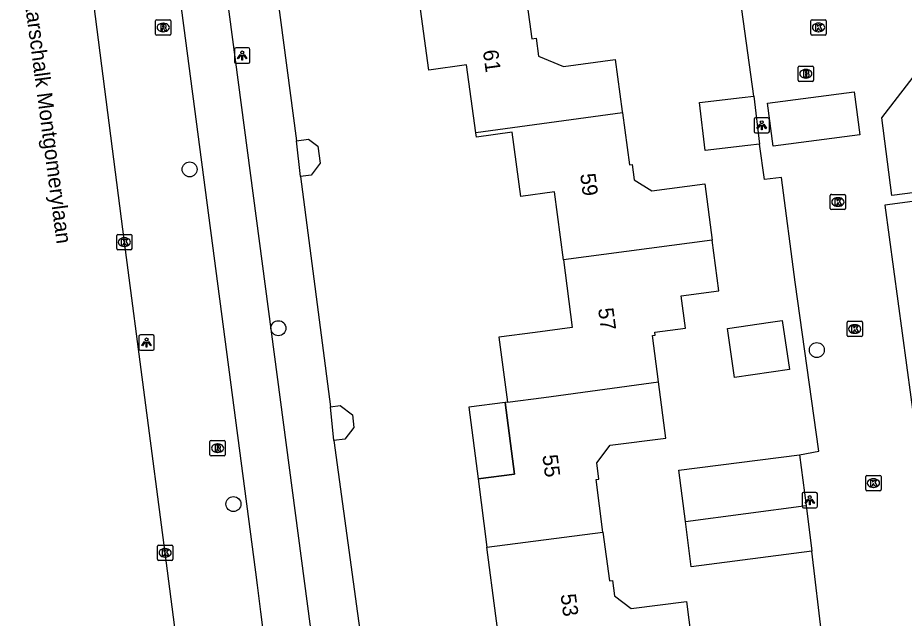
# Model space of a CAD drawing. Extents: x 161084 to 161928, y 385355 to 386522.
# Drawn here: x 161147.4 to 161205.4, y 386075.9 to 386115.2 of the extents above; entities that cross this region are included whole.
import ezdxf

# ---------------------------------------------------------------- set-up
doc = ezdxf.new("R2010")
doc.units = 0
for name, color, linetype in [('IMGEO_Boom', 7, 'Continuous'), ('IMGEO_Brandkraan', 7, 'Continuous'), ('IMGEO_Fietspad_gesloten', 7, 'Continuous'), ('IMGEO_Kolk', 7, 'Continuous'), ('IMGEO_Lichtpunt', 7, 'Continuous'), ('IMGEO_Openbare_ruimte_label', 7, 'Continuous'), ('IMGEO_OVBaan_gesloten', 7, 'Continuous'), ('IMGEO_Pand', 7, 'Continuous'), ('IMGEO_Pand_nummerreeks', 7, 'Continuous'), ('IMGEO_Pand_overbouw', 7, 'Continuous'), ('IMGEO_Rijbaan_lokaal_open', 7, 'Continuous'), ('IMGEO_Rioolput', 7, 'Continuous'), ('IMGEO_Voetpad_open', 7, 'Continuous')]:
    doc.layers.add(name, color=color, linetype=linetype)

msp = doc.modelspace()

# ---------------------------------------------------------------- linework, layer by layer
at = {"layer": 'IMGEO_Boom'}
for centre in [(161158.68, 386105.239), (161164.481, 386094.854), (161199.666, 386093.427), (161161.542, 386083.355)]:
    msp.add_circle(centre, 0.489, dxfattribs=at)
at = {"layer": 'IMGEO_Brandkraan'}
for p, q in [((161198.449, 386111.065), (161198.449, 386111.917)), ((161198.524, 386111.991), (161199.376, 386111.991)), ((161199.45, 386111.917), (161199.45, 386111.065)), ((161198.96, 386111.211), (161198.935, 386111.211)), ((161198.937, 386111.771), (161198.962, 386111.771)), ((161199.376, 386110.991), (161198.524, 386110.991))]:
    msp.add_line(p, q, dxfattribs=at)
for points in [[(161198.449, 386111.065), (161198.449, 386111.917)], [(161198.524, 386111.991), (161199.376, 386111.991)], [(161199.45, 386111.917), (161199.45, 386111.065)], [(161198.797, 386111.691), (161198.797, 386111.291), (161199.01, 386111.291)], [(161199.028, 386111.691), (161198.797, 386111.691)], [(161198.976, 386111.61), (161198.922, 386111.61), (161198.922, 386111.534)], [(161198.922, 386111.534), (161198.975, 386111.534)], [(161198.984, 386111.458), (161198.922, 386111.458), (161198.922, 386111.377)], [(161198.922, 386111.377), (161198.984, 386111.377)], [(161199.376, 386110.991), (161198.524, 386110.991)]]:
    msp.add_lwpolyline(points, dxfattribs=at)
for centre, radius, start, end in [((161198.526, 386111.915), 0.0765, 91.55205, 178.44795), ((161198.526, 386111.915), 0.0765, 91.55205, 178.44795), ((161199.374, 386111.915), 0.0765, 1.55205, 88.44795), ((161199.374, 386111.915), 0.0765, 1.55205, 88.44795), ((161198.977, 386111.572), 0.0379, 267.82845, 90.93552), ((161198.985, 386111.417), 0.0404, 269.87594, 90.50774), ((161199.016, 386111.542), 0.251, 268.66757, 293.53466), ((161199.032, 386111.546), 0.145, 59.4692, 91.53667), ((161199.057, 386111.593), 0.0922, 285.51372, 58.15012), ((161199.062, 386111.401), 0.105, 301.31148, 78.98903), ((161198.526, 386111.067), 0.0765, 181.55205, 268.44795), ((161198.526, 386111.067), 0.0765, 181.55205, 268.44795), ((161199.374, 386111.067), 0.0765, 271.55205, 358.44795), ((161199.374, 386111.067), 0.0765, 271.55205, 358.44795)]:
    msp.add_arc(centre, radius, start, end, dxfattribs=at)
for centre, major_axis, ratio, start_param, end_param in [((161198.936, 386111.491), (-0.387, 0.002), 0.722429, 4.712389, 7.853982), ((161198.961, 386111.491), (-0.39, 0.002), 0.717154, 1.570796, 4.712389)]:
    msp.add_ellipse(centre, major_axis=major_axis, ratio=ratio, start_param=start_param, end_param=end_param, dxfattribs=at)
at = {"layer": 'IMGEO_Fietspad_gesloten'}
for points in [[(161163.009, 386078.911), (161157.717, 386119.144), (161156.332, 386131.161), (161154.639, 386141.624)], [(161166.599, 386075.195), (161159.109, 386131.85), (161158.613, 386135.495), (161158.527, 386136.476), (161158.508, 386136.957), (161158.694, 386138.756), (161158.914, 386139.531)]]:
    msp.add_lwpolyline(points, dxfattribs=at)
msp.add_arc((160918.944, 386047.246), 246.11, 0.90262, 7.39227, dxfattribs=at)
at = {"layer": 'IMGEO_Kolk'}
for p, q in [((161199.277, 386114.093), (161199.277, 386114.945)), ((161199.352, 386115.019), (161200.204, 386115.019)), ((161199.765, 386114.799), (161199.79, 386114.799)), ((161200.278, 386114.945), (161200.278, 386114.093)), ((161199.788, 386114.239), (161199.763, 386114.239)), ((161200.204, 386114.019), (161199.352, 386114.019)), ((161200.544, 386102.68), (161200.544, 386103.532)), ((161200.619, 386103.606), (161201.471, 386103.606)), ((161201.032, 386103.386), (161201.057, 386103.386)), ((161201.545, 386103.532), (161201.545, 386102.68)), ((161201.471, 386102.606), (161200.619, 386102.606)), ((161201.055, 386102.826), (161201.03, 386102.826)), ((161153.911, 386100.059), (161153.911, 386100.911)), ((161153.986, 386100.985), (161154.838, 386100.985)), ((161154.912, 386100.911), (161154.912, 386100.059)), ((161154.422, 386100.205), (161154.397, 386100.205)), ((161154.399, 386100.765), (161154.424, 386100.765)), ((161154.838, 386099.985), (161153.986, 386099.985)), ((161201.641, 386094.377), (161201.641, 386095.229)), ((161201.716, 386095.303), (161202.568, 386095.303)), ((161202.129, 386095.083), (161202.154, 386095.083)), ((161202.642, 386095.229), (161202.642, 386094.377)), ((161202.152, 386094.523), (161202.127, 386094.523)), ((161202.568, 386094.303), (161201.716, 386094.303)), ((161202.867, 386084.303), (161202.867, 386085.155)), ((161202.942, 386085.229), (161203.794, 386085.229)), ((161203.868, 386085.155), (161203.868, 386084.303)), ((161203.355, 386085.009), (161203.38, 386085.009)), ((161203.794, 386084.229), (161202.942, 386084.229)), ((161203.378, 386084.449), (161203.353, 386084.449)), ((161156.578, 386079.744), (161156.578, 386080.596)), ((161156.653, 386080.67), (161157.505, 386080.67)), ((161157.579, 386080.596), (161157.579, 386079.744)), ((161157.066, 386080.45), (161157.091, 386080.45)), ((161157.505, 386079.67), (161156.653, 386079.67)), ((161157.089, 386079.89), (161157.064, 386079.89))]:
    msp.add_line(p, q, dxfattribs=at)
for points in [[(161199.277, 386114.093), (161199.277, 386114.945)], [(161199.352, 386115.019), (161200.204, 386115.019)], [(161199.598, 386114.719), (161199.721, 386114.719), (161199.721, 386114.568), (161199.851, 386114.719), (161200.015, 386114.719), (161199.869, 386114.568), (161200.022, 386114.319), (161199.87, 386114.319), (161199.785, 386114.483), (161199.721, 386114.416), (161199.721, 386114.319), (161199.598, 386114.319), (161199.598, 386114.719)], [(161200.278, 386114.945), (161200.278, 386114.093)], [(161200.204, 386114.019), (161199.352, 386114.019)], [(161200.544, 386102.68), (161200.544, 386103.532)], [(161200.619, 386103.606), (161201.471, 386103.606)], [(161200.865, 386103.306), (161200.988, 386103.306), (161200.988, 386103.155), (161201.118, 386103.306), (161201.282, 386103.306), (161201.136, 386103.155), (161201.289, 386102.906), (161201.137, 386102.906), (161201.052, 386103.07), (161200.988, 386103.003), (161200.988, 386102.906), (161200.865, 386102.906), (161200.865, 386103.306)], [(161201.545, 386103.532), (161201.545, 386102.68)], [(161201.471, 386102.606), (161200.619, 386102.606)], [(161153.911, 386100.059), (161153.911, 386100.911)], [(161153.986, 386100.985), (161154.838, 386100.985)], [(161154.912, 386100.911), (161154.912, 386100.059)], [(161154.232, 386100.685), (161154.355, 386100.685), (161154.355, 386100.534), (161154.485, 386100.685), (161154.649, 386100.685), (161154.503, 386100.534), (161154.656, 386100.285), (161154.504, 386100.285), (161154.419, 386100.449), (161154.355, 386100.382), (161154.355, 386100.285), (161154.232, 386100.285), (161154.232, 386100.685)], [(161154.838, 386099.985), (161153.986, 386099.985)], [(161201.641, 386094.377), (161201.641, 386095.229)], [(161201.716, 386095.303), (161202.568, 386095.303)], [(161201.962, 386095.003), (161202.085, 386095.003), (161202.085, 386094.852), (161202.215, 386095.003), (161202.379, 386095.003), (161202.233, 386094.852), (161202.386, 386094.603), (161202.234, 386094.603), (161202.149, 386094.767), (161202.085, 386094.7), (161202.085, 386094.603), (161201.962, 386094.603), (161201.962, 386095.003)], [(161202.642, 386095.229), (161202.642, 386094.377)], [(161202.568, 386094.303), (161201.716, 386094.303)], [(161202.867, 386084.303), (161202.867, 386085.155)], [(161202.942, 386085.229), (161203.794, 386085.229)], [(161203.868, 386085.155), (161203.868, 386084.303)], [(161203.188, 386084.929), (161203.311, 386084.929), (161203.311, 386084.778), (161203.441, 386084.929), (161203.605, 386084.929), (161203.459, 386084.778), (161203.612, 386084.529), (161203.46, 386084.529), (161203.375, 386084.693), (161203.311, 386084.626), (161203.311, 386084.529), (161203.188, 386084.529), (161203.188, 386084.929)], [(161203.794, 386084.229), (161202.942, 386084.229)], [(161156.578, 386079.744), (161156.578, 386080.596)], [(161156.653, 386080.67), (161157.505, 386080.67)], [(161157.579, 386080.596), (161157.579, 386079.744)], [(161156.899, 386080.37), (161157.022, 386080.37), (161157.022, 386080.219), (161157.152, 386080.37), (161157.316, 386080.37), (161157.17, 386080.219), (161157.323, 386079.97), (161157.171, 386079.97), (161157.086, 386080.134), (161157.022, 386080.067), (161157.022, 386079.97), (161156.899, 386079.97), (161156.899, 386080.37)], [(161157.505, 386079.67), (161156.653, 386079.67)]]:
    msp.add_lwpolyline(points, dxfattribs=at)
for centre, start, end in [((161199.354, 386114.943), 91.55205, 178.44795), ((161199.354, 386114.943), 91.55205, 178.44795), ((161200.202, 386114.943), 1.55205, 88.44795), ((161200.202, 386114.943), 1.55205, 88.44795), ((161199.354, 386114.095), 181.55205, 268.44795), ((161199.354, 386114.095), 181.55205, 268.44795), ((161200.202, 386114.095), 271.55205, 358.44795), ((161200.202, 386114.095), 271.55205, 358.44795), ((161200.621, 386103.53), 91.55205, 178.44795), ((161200.621, 386103.53), 91.55205, 178.44795), ((161201.469, 386103.53), 1.55205, 88.44795), ((161201.469, 386103.53), 1.55205, 88.44795), ((161200.621, 386102.682), 181.55205, 268.44795), ((161200.621, 386102.682), 181.55205, 268.44795), ((161201.469, 386102.682), 271.55205, 358.44795), ((161201.469, 386102.682), 271.55205, 358.44795), ((161153.988, 386100.909), 91.55205, 178.44795), ((161153.988, 386100.909), 91.55205, 178.44795), ((161154.836, 386100.909), 1.55205, 88.44795), ((161154.836, 386100.909), 1.55205, 88.44795), ((161153.988, 386100.061), 181.55205, 268.44795), ((161153.988, 386100.061), 181.55205, 268.44795), ((161154.836, 386100.061), 271.55205, 358.44795), ((161154.836, 386100.061), 271.55205, 358.44795), ((161201.718, 386095.227), 91.55205, 178.44795), ((161201.718, 386095.227), 91.55205, 178.44795), ((161202.566, 386095.227), 1.55205, 88.44795), ((161202.566, 386095.227), 1.55205, 88.44795), ((161201.718, 386094.379), 181.55205, 268.44795), ((161201.718, 386094.379), 181.55205, 268.44795), ((161202.566, 386094.379), 271.55205, 358.44795), ((161202.566, 386094.379), 271.55205, 358.44795), ((161202.944, 386085.153), 91.55205, 178.44795), ((161202.944, 386085.153), 91.55205, 178.44795), ((161203.792, 386085.153), 1.55205, 88.44795), ((161203.792, 386085.153), 1.55205, 88.44795), ((161202.944, 386084.305), 181.55205, 268.44795), ((161202.944, 386084.305), 181.55205, 268.44795), ((161203.792, 386084.305), 271.55205, 358.44795), ((161203.792, 386084.305), 271.55205, 358.44795), ((161156.655, 386080.594), 91.55205, 178.44795), ((161156.655, 386080.594), 91.55205, 178.44795), ((161157.503, 386080.594), 1.55205, 88.44795), ((161157.503, 386080.594), 1.55205, 88.44795), ((161156.655, 386079.746), 181.55205, 268.44795), ((161156.655, 386079.746), 181.55205, 268.44795), ((161157.503, 386079.746), 271.55205, 358.44795), ((161157.503, 386079.746), 271.55205, 358.44795)]:
    msp.add_arc(centre, 0.0765, start, end, dxfattribs=at)
for centre, major_axis, ratio, start_param, end_param in [((161199.764, 386114.519), (-0.387, 0.002), 0.722429, 4.712389, 7.853982), ((161199.789, 386114.519), (-0.39, 0.002), 0.717154, 1.570796, 4.712389), ((161201.031, 386103.106), (-0.387, 0.002), 0.722429, 4.712389, 7.853982), ((161201.056, 386103.106), (-0.39, 0.002), 0.717154, 1.570796, 4.712389), ((161154.398, 386100.485), (-0.387, 0.002), 0.722429, 4.712389, 7.853982), ((161154.423, 386100.485), (-0.39, 0.002), 0.717154, 1.570796, 4.712389), ((161202.128, 386094.803), (-0.387, 0.002), 0.722429, 4.712389, 7.853982), ((161202.153, 386094.803), (-0.39, 0.002), 0.717154, 1.570796, 4.712389), ((161203.354, 386084.729), (-0.387, 0.002), 0.722429, 4.712389, 7.853982), ((161203.379, 386084.729), (-0.39, 0.002), 0.717154, 1.570796, 4.712389), ((161157.065, 386080.17), (-0.387, 0.002), 0.722429, 4.712389, 7.853982), ((161157.09, 386080.17), (-0.39, 0.002), 0.717154, 1.570796, 4.712389)]:
    msp.add_ellipse(centre, major_axis=major_axis, ratio=ratio, start_param=start_param, end_param=end_param, dxfattribs=at)
at = {"layer": 'IMGEO_Lichtpunt'}
for p, q in [((161161.615, 386113.085), (161161.615, 386112.278)), ((161161.615, 386113.085), (161161.615, 386112.278)), ((161162.517, 386113.18), (161161.709, 386113.18)), ((161162.517, 386113.18), (161161.709, 386113.18)), ((161162.611, 386112.278), (161162.611, 386113.085)), ((161162.611, 386112.278), (161162.611, 386113.085)), ((161161.709, 386112.184), (161162.517, 386112.184)), ((161161.709, 386112.184), (161162.517, 386112.184)), ((161195.569, 386108.522), (161195.569, 386107.715)), ((161195.569, 386108.522), (161195.569, 386107.715)), ((161196.471, 386108.617), (161195.663, 386108.617)), ((161196.471, 386108.617), (161195.663, 386108.617)), ((161196.565, 386107.715), (161196.565, 386108.522)), ((161196.565, 386107.715), (161196.565, 386108.522)), ((161195.663, 386107.621), (161196.471, 386107.621)), ((161195.663, 386107.621), (161196.471, 386107.621)), ((161156.265, 386094.414), (161155.457, 386094.414)), ((161156.265, 386094.414), (161155.457, 386094.414)), ((161155.363, 386094.319), (161155.363, 386093.512)), ((161155.363, 386094.319), (161155.363, 386093.512)), ((161156.359, 386093.512), (161156.359, 386094.319)), ((161156.359, 386093.512), (161156.359, 386094.319)), ((161155.457, 386093.418), (161156.265, 386093.418)), ((161155.457, 386093.418), (161156.265, 386093.418)), ((161198.707, 386084.015), (161198.707, 386083.208)), ((161198.707, 386084.015), (161198.707, 386083.208)), ((161199.609, 386084.11), (161198.801, 386084.11)), ((161199.609, 386084.11), (161198.801, 386084.11)), ((161199.703, 386083.208), (161199.703, 386084.015)), ((161199.703, 386083.208), (161199.703, 386084.015)), ((161198.801, 386083.114), (161199.609, 386083.114)), ((161198.801, 386083.114), (161199.609, 386083.114))]:
    msp.add_line(p, q, dxfattribs=at)
for points in [[(161161.989, 386112.749), (161162.028, 386112.721), (161161.84, 386112.459), (161161.802, 386112.486), (161161.989, 386112.749)], [(161162.091, 386112.701), (161162.138, 386112.701), (161162.138, 386112.379), (161162.091, 386112.379), (161162.091, 386112.701)], [(161162.201, 386112.721), (161162.239, 386112.748), (161162.426, 386112.486), (161162.387, 386112.458), (161162.201, 386112.721)], [(161195.943, 386108.186), (161195.982, 386108.158), (161195.794, 386107.896), (161195.756, 386107.923), (161195.943, 386108.186)], [(161196.045, 386108.138), (161196.092, 386108.138), (161196.092, 386107.816), (161196.045, 386107.816), (161196.045, 386108.138)], [(161196.155, 386108.158), (161196.193, 386108.185), (161196.38, 386107.923), (161196.341, 386107.895), (161196.155, 386108.158)], [(161155.737, 386093.983), (161155.776, 386093.955), (161155.588, 386093.693), (161155.55, 386093.72), (161155.737, 386093.983)], [(161155.839, 386093.935), (161155.886, 386093.935), (161155.886, 386093.613), (161155.839, 386093.613), (161155.839, 386093.935)], [(161155.949, 386093.955), (161155.987, 386093.982), (161156.174, 386093.72), (161156.135, 386093.692), (161155.949, 386093.955)], [(161199.081, 386083.679), (161199.12, 386083.651), (161198.932, 386083.389), (161198.894, 386083.416), (161199.081, 386083.679)], [(161199.183, 386083.631), (161199.23, 386083.631), (161199.23, 386083.309), (161199.183, 386083.309), (161199.183, 386083.631)], [(161199.293, 386083.651), (161199.331, 386083.678), (161199.518, 386083.416), (161199.479, 386083.388), (161199.293, 386083.651)]]:
    msp.add_lwpolyline(points, dxfattribs=at)
for centre in [(161162.114, 386112.883), (161196.068, 386108.32), (161155.862, 386094.117), (161199.206, 386083.813)]:
    msp.add_circle(centre, 0.0994, dxfattribs=at)
for centre, start, end in [((161161.709, 386113.085), 90, 180), ((161161.709, 386113.085), 90, 180), ((161162.517, 386113.085), 0, 90), ((161162.517, 386113.085), 0, 90), ((161161.709, 386112.278), 180, 270), ((161161.709, 386112.278), 180, 270), ((161162.517, 386112.278), 270, 0), ((161162.517, 386112.278), 270, 360), ((161195.663, 386108.522), 90, 180), ((161195.663, 386108.522), 90, 180), ((161196.471, 386108.522), 0, 90), ((161196.471, 386108.522), 0, 90), ((161195.663, 386107.715), 180, 270), ((161195.663, 386107.715), 180, 270), ((161196.471, 386107.715), 270, 0), ((161196.471, 386107.715), 270, 360), ((161155.457, 386094.319), 90, 180), ((161155.457, 386094.319), 90, 180), ((161156.265, 386094.319), 0, 90), ((161156.265, 386094.319), 0, 90), ((161155.457, 386093.512), 180, 270), ((161155.457, 386093.512), 180, 270), ((161156.265, 386093.512), 270, 0), ((161156.265, 386093.512), 270, 360), ((161198.801, 386084.015), 90, 180), ((161198.801, 386084.015), 90, 180), ((161199.609, 386084.015), 0, 90), ((161199.609, 386084.015), 0, 90), ((161198.801, 386083.208), 180, 270), ((161198.801, 386083.208), 180, 270), ((161199.609, 386083.208), 270, 0), ((161199.609, 386083.208), 270, 360)]:
    msp.add_arc(centre, 0.0946, start, end, dxfattribs=at)
at = {"layer": 'IMGEO_OVBaan_gesloten'}
msp.add_lwpolyline([(161194.813, 385794.299), (161194.675, 385795.33), (161194.437, 385797.117), (161192.506, 385812.149), (161181.599, 385894.516), (161177.056, 385929.432), (161176.3, 385935.247), (161173.593, 385955.119), (161163.181, 386034.035), (161162.806, 386036.478), (161159.857, 386058.81), (161157.079, 386080.17), (161154.412, 386100.485), (161151.938, 386119.836), (161149.318, 386139.173), (161149.083, 386140.767)], dxfattribs=at)
at = {"layer": 'IMGEO_Pand'}
for points in [[(161180.584, 386117.131), (161181.043, 386113.774), (161181.316, 386113.812), (161181.478, 386112.629), (161183.121, 386111.958), (161186.49, 386112.419), (161186.954, 386109.028), (161186.967, 386108.928)], [(161177.381, 386107.62), (161176.774, 386112.067), (161174.311, 386111.731), (161173.701, 386116.19)], [(161208.861, 386103.523), (161208.789, 386104.076), (161204.572, 386103.529), (161203.913, 386108.607), (161206.552, 386112.033), (161211.281, 386112.647)], [(161195.924, 386106.891), (161195.15, 386106.801), (161192.368, 386106.477), (161192.002, 386109.616), (161194.784, 386109.94), (161195.558, 386110.03)], [(161195.558, 386110.03), (161195.924, 386106.891)], [(161186.967, 386108.928), (161177.381, 386107.62)], [(161186.967, 386108.928), (161187.432, 386105.532), (161187.591, 386105.554), (161187.727, 386104.558), (161188.888, 386103.828), (161192.339, 386104.295), (161192.822, 386100.599)], [(161183.101, 386099.328), (161182.521, 386103.767), (161180.324, 386103.467), (161179.75, 386107.661), (161177.419, 386107.342), (161177.381, 386107.62)], [(161192.822, 386100.599), (161183.101, 386099.328)], [(161189.315, 386091.347), (161188.919, 386094.377), (161189.106, 386094.401), (161189.082, 386094.588), (161191.081, 386094.849), (161190.804, 386096.971), (161193.254, 386097.291), (161192.822, 386100.599)], [(161183.101, 386099.328), (161183.681, 386094.891), (161181.264, 386094.575), (161178.894, 386094.265), (161179.45, 386090.015)], [(161196.637, 386095.253), (161197.408, 386095.367), (161197.883, 386092.153), (161194.295, 386091.622), (161193.82, 386094.836), (161196.637, 386095.253)], [(161179.45, 386090.015), (161181.819, 386090.325), (161189.315, 386091.347)], [(161185.69, 386081.519), (161185.241, 386084.955), (161185.419, 386084.978), (161185.279, 386086.053), (161186.161, 386087.2), (161189.795, 386087.675), (161189.315, 386091.347)], [(161179.45, 386090.015), (161179.303, 386089.996), (161179.915, 386085.311), (161177.526, 386084.998), (161178.11, 386080.528)], [(161191.081, 386082.224), (161190.651, 386085.572), (161198.535, 386086.585)], [(161198.535, 386086.585), (161198.963, 386083.254)], [(161191.081, 386082.224), (161198.963, 386083.254)], [(161198.963, 386083.254), (161199.347, 386080.268)], [(161199.347, 386080.268), (161191.463, 386079.255), (161191.081, 386082.224)], [(161178.11, 386080.528), (161185.69, 386081.519)], [(161185.69, 386081.519), (161186.107, 386078.331), (161186.306, 386078.357), (161186.436, 386077.356), (161187.524, 386076.519), (161191.14, 386076.992), (161191.633, 386073.219)], [(161184.027, 386072.046), (161181.734, 386071.748), (161181.647, 386072.418), (161179.206, 386072.136), (161178.694, 386076.056), (161178.11, 386080.528)]]:
    msp.add_lwpolyline(points, dxfattribs=at)
at = {"layer": 'IMGEO_Pand_overbouw'}
msp.add_lwpolyline([(161177.526, 386084.998), (161179.915, 386085.311), (161179.303, 386089.996), (161176.914, 386089.684)], close=True, dxfattribs=at)
at = {"layer": 'IMGEO_Rijbaan_lokaal_open'}
for points in [[(161195.558, 386110.03), (161194.774, 386115.698), (161195.959, 386116.087), (161196.529, 386116.734), (161197.945, 386118.341), (161197.87, 386118.89), (161197.818, 386119.923), (161215.635, 386122.52), (161226.565, 386124.113)], [(161196.812, 386106.757), (161196.447, 386109.565), (161202.11, 386110.299), (161202.475, 386107.492), (161196.812, 386106.757)], [(161198.535, 386086.585), (161199.791, 386086.818), (161198.244, 386097.856), (161197.358, 386104.703), (161196.243, 386104.573), (161195.924, 386106.891)], [(161208.861, 386103.523), (161204.109, 386102.907), (161206.104, 386088.242), (161210.969, 386088.92)], [(161200.017, 386074.574), (161199.347, 386080.268)]]:
    msp.add_lwpolyline(points, dxfattribs=at)
at = {"layer": 'IMGEO_Rioolput'}
for p, q in [((161156.451, 386114.088), (161156.451, 386114.94)), ((161156.526, 386115.014), (161157.378, 386115.014)), ((161156.939, 386114.794), (161156.964, 386114.794)), ((161157.452, 386114.94), (161157.452, 386114.088)), ((161156.962, 386114.234), (161156.937, 386114.234)), ((161157.378, 386114.014), (161156.526, 386114.014)), ((161160.082, 386087.51), (161160.934, 386087.51)), ((161160.007, 386086.584), (161160.007, 386087.436)), ((161160.495, 386087.29), (161160.52, 386087.29)), ((161161.008, 386087.436), (161161.008, 386086.584)), ((161160.934, 386086.51), (161160.082, 386086.51)), ((161160.518, 386086.73), (161160.493, 386086.73))]:
    msp.add_line(p, q, dxfattribs=at)
for points in [[(161156.451, 386114.088), (161156.451, 386114.94)], [(161156.526, 386115.014), (161157.378, 386115.014)], [(161157.04, 386114.712), (161156.788, 386114.714), (161156.788, 386114.314)], [(161157.452, 386114.94), (161157.452, 386114.088)], [(161156.788, 386114.314), (161156.912, 386114.314), (161156.912, 386114.476), (161156.923, 386114.476)], [(161156.966, 386114.633), (161156.912, 386114.633), (161156.912, 386114.552)], [(161156.912, 386114.552), (161156.964, 386114.552)], [(161156.97, 386114.447), (161157.041, 386114.314), (161157.181, 386114.314), (161157.116, 386114.44)], [(161157.378, 386114.014), (161156.526, 386114.014)], [(161160.082, 386087.51), (161160.934, 386087.51)], [(161160.007, 386086.584), (161160.007, 386087.436)], [(161160.596, 386087.208), (161160.344, 386087.21), (161160.344, 386086.81)], [(161160.344, 386086.81), (161160.468, 386086.81), (161160.468, 386086.972), (161160.479, 386086.972)], [(161160.522, 386087.129), (161160.468, 386087.129), (161160.468, 386087.048)], [(161160.468, 386087.048), (161160.52, 386087.048)], [(161160.526, 386086.943), (161160.597, 386086.81), (161160.737, 386086.81), (161160.672, 386086.936)], [(161161.008, 386087.436), (161161.008, 386086.584)], [(161160.934, 386086.51), (161160.082, 386086.51)]]:
    msp.add_lwpolyline(points, dxfattribs=at)
for centre, radius, start, end in [((161156.528, 386114.938), 0.0765, 91.55205, 178.44795), ((161156.528, 386114.938), 0.0765, 91.55205, 178.44795), ((161157.039, 386114.602), 0.109, 350.36119, 89.41601), ((161157.376, 386114.938), 0.0765, 1.55205, 88.44795), ((161157.376, 386114.938), 0.0765, 1.55205, 88.44795), ((161156.922, 386114.423), 0.0533, 26.02933, 88.69889), ((161156.948, 386114.741), 0.19, 274.7715, 282.96867), ((161156.972, 386114.537), 0.0964, 77.00612, 93.18647), ((161156.986, 386114.594), 0.0378, 276.66336, 79.67722), ((161157.037, 386114.602), 0.112, 277.58423, 350.98172), ((161157.021, 386114.387), 0.108, 29.51342, 73.79051), ((161156.528, 386114.09), 0.0765, 181.55205, 268.44795), ((161156.528, 386114.09), 0.0765, 181.55205, 268.44795), ((161157.376, 386114.09), 0.0765, 271.55205, 358.44795), ((161157.376, 386114.09), 0.0765, 271.55205, 358.44795), ((161160.084, 386087.434), 0.0765, 91.55205, 178.44795), ((161160.084, 386087.434), 0.0765, 91.55205, 178.44795), ((161160.932, 386087.434), 0.0765, 1.55205, 88.44795), ((161160.932, 386087.434), 0.0765, 1.55205, 88.44795), ((161160.478, 386086.919), 0.0533, 26.02933, 88.69889), ((161160.504, 386087.237), 0.19, 274.7715, 282.96867), ((161160.528, 386087.033), 0.0964, 77.00612, 93.18647), ((161160.542, 386087.09), 0.0378, 276.66336, 79.67722), ((161160.595, 386087.098), 0.109, 350.36119, 89.41601), ((161160.593, 386087.098), 0.112, 277.58423, 350.98172), ((161160.577, 386086.883), 0.108, 29.51342, 73.79051), ((161160.084, 386086.586), 0.0765, 181.55205, 268.44795), ((161160.084, 386086.586), 0.0765, 181.55205, 268.44795), ((161160.932, 386086.586), 0.0765, 271.55205, 358.44795), ((161160.932, 386086.586), 0.0765, 271.55205, 358.44795)]:
    msp.add_arc(centre, radius, start, end, dxfattribs=at)
for centre, major_axis, ratio, start_param, end_param in [((161156.938, 386114.514), (-0.387, 0.002), 0.722429, 4.712389, 7.853982), ((161156.963, 386114.514), (-0.39, 0.002), 0.717154, 1.570796, 4.712389), ((161160.494, 386087.01), (-0.387, 0.002), 0.722429, 4.712389, 7.853982), ((161160.519, 386087.01), (-0.39, 0.002), 0.717154, 1.570796, 4.712389)]:
    msp.add_ellipse(centre, major_axis=major_axis, ratio=ratio, start_param=start_param, end_param=end_param, dxfattribs=at)
at = {"layer": 'IMGEO_Voetpad_open'}
for points in [[(161163.578, 386122.93), (161165.653, 386107.11)], [(161165.653, 386107.11), (161166.451, 386107.214), (161167.058, 386106.748), (161167.205, 386105.633), (161166.617, 386104.868), (161165.923, 386104.777)], [(161165.923, 386104.777), (161165.653, 386107.11)], [(161165.923, 386104.777), (161167.88, 386089.711)], [(161167.88, 386089.711), (161168.514, 386089.794), (161169.313, 386089.181), (161169.419, 386088.37), (161168.826, 386087.598), (161168.102, 386087.503)], [(161168.102, 386087.503), (161167.88, 386089.711)], [(161168.102, 386087.503), (161170.273, 386071.572)]]:
    msp.add_lwpolyline(points, dxfattribs=at)

# ---------------------------------------------------------------- texts
at = {"layer": 'IMGEO_Openbare_ruimte_label'}
msp.add_text('Veldmaarschalk Montgomerylaan', height=1, rotation=277.53025, dxfattribs=at).set_placement((161147.394, 386120.004))
at = {"layer": 'IMGEO_Pand_nummerreeks'}
for s, rotation, p in [('61', 277.77923, (161177.838, 386112.999)), ('59', 277.60543, (161184.194, 386104.918)), ('57', 277.60294, (161185.368, 386096.127)), ('55', 277.44824, (161181.727, 386086.532)), ('53', 277.44842, (161182.917, 386077.43))]:
    msp.add_text(s, height=1, rotation=rotation, dxfattribs=at).set_placement(p)

doc.saveas('drawing.dxf')
